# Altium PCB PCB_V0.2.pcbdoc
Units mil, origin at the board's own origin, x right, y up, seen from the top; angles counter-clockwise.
Board outline 2400 x 1790 mil, 2 copper layers (Top Layer, Bottom Layer); 38 components, 36 nets, 174 pads, 42 vias.
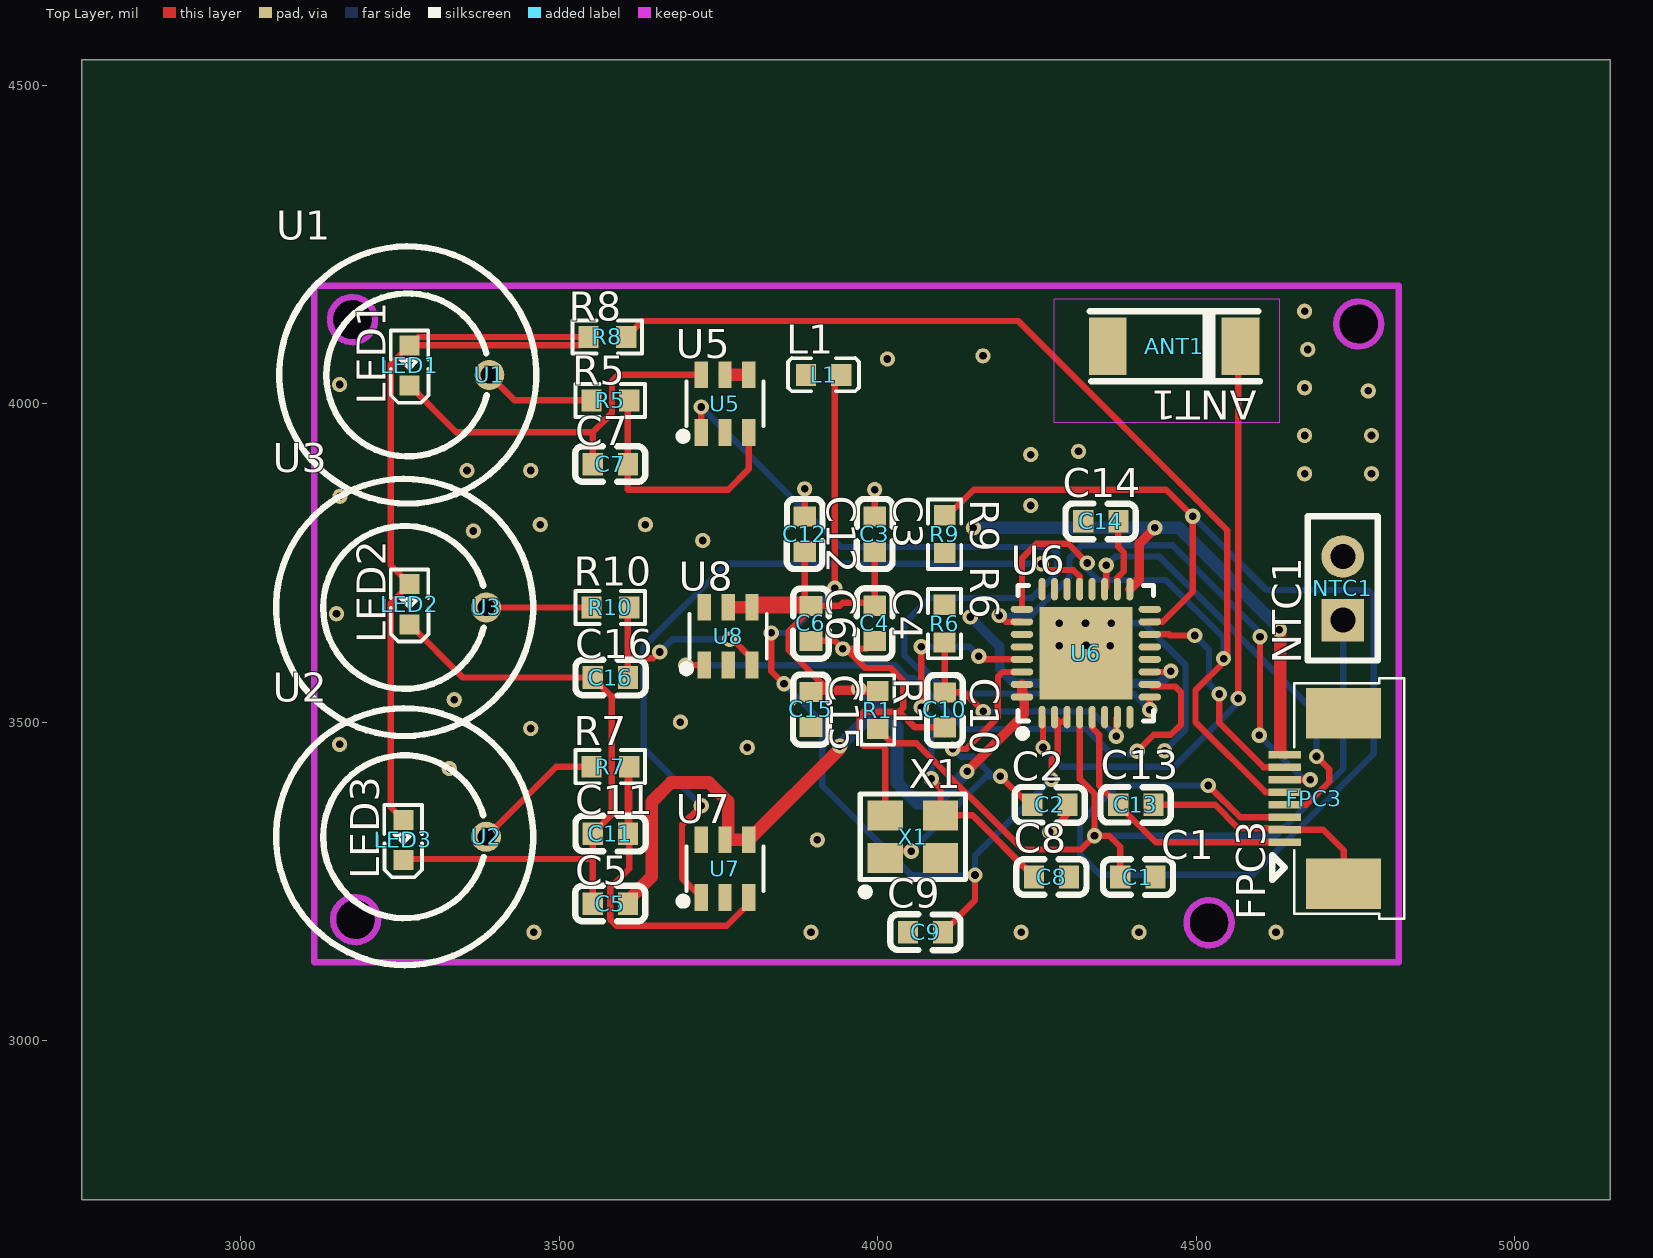
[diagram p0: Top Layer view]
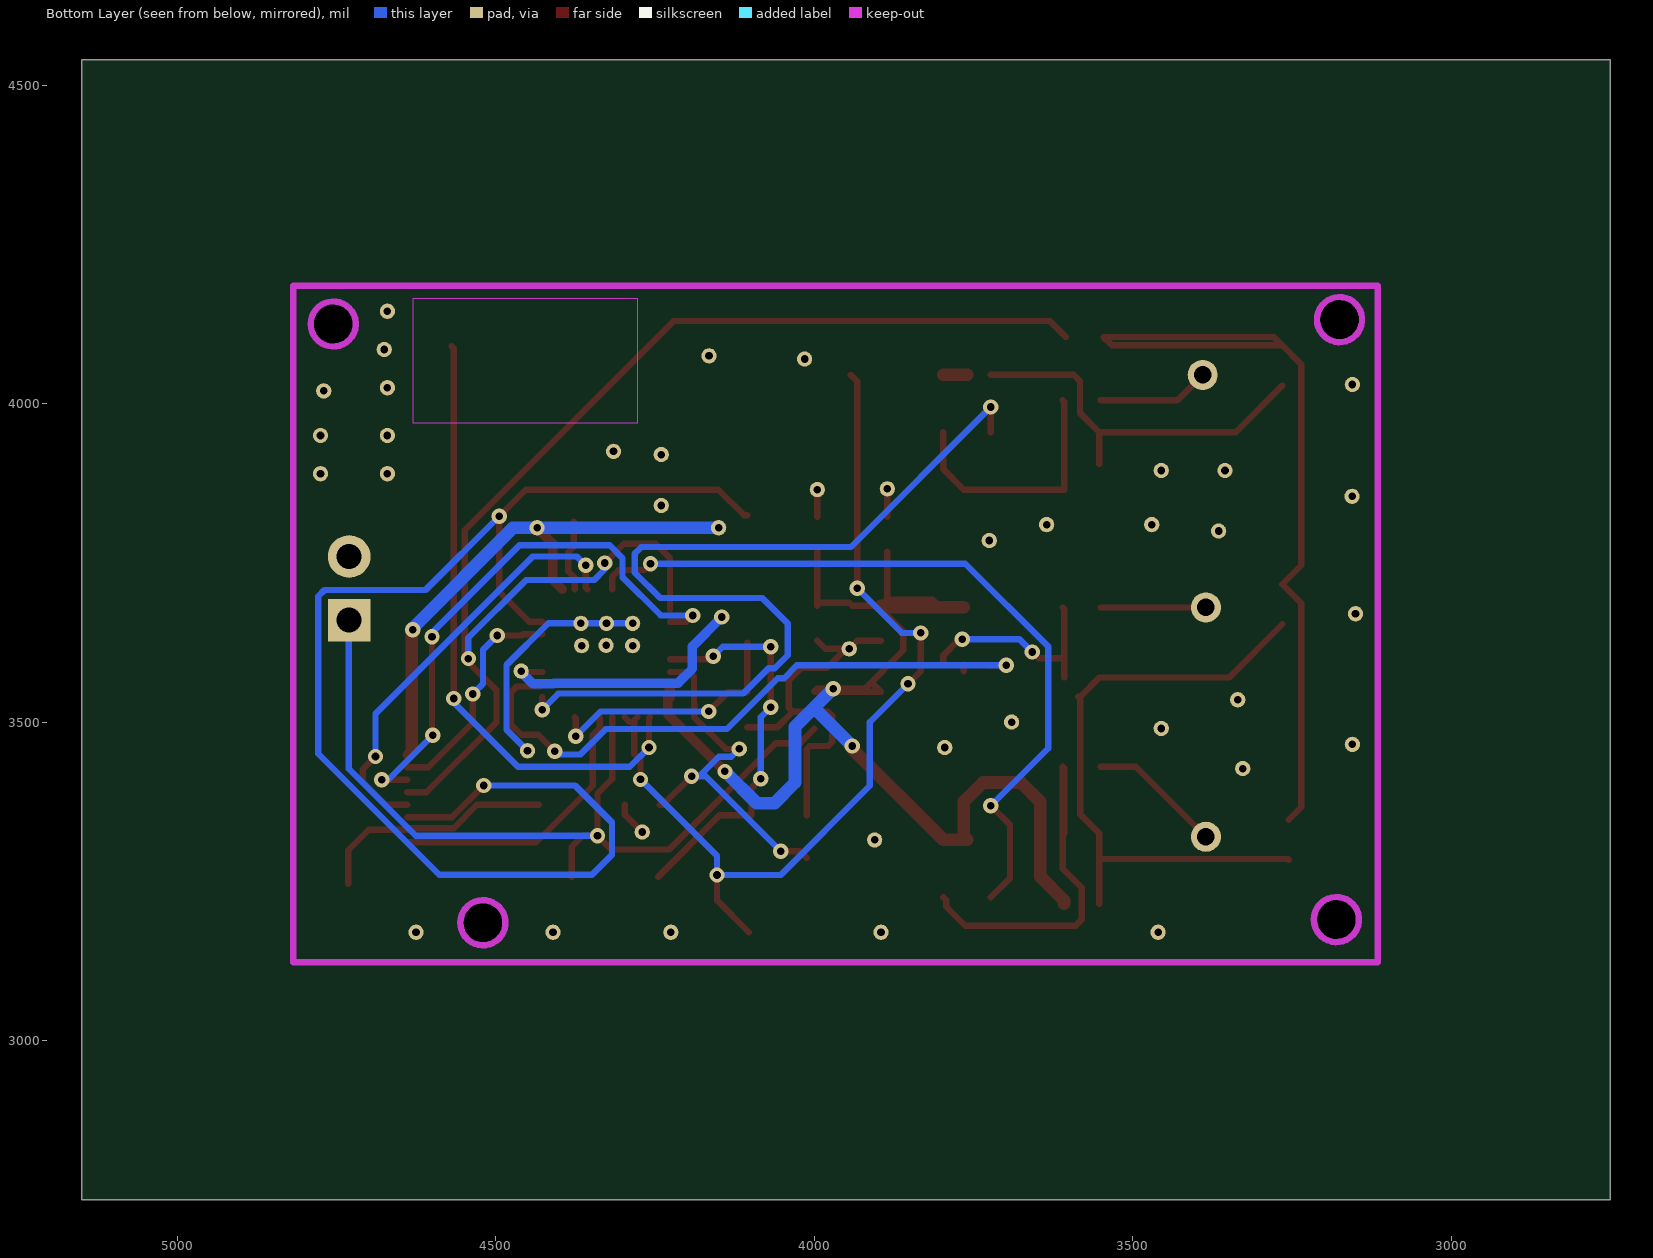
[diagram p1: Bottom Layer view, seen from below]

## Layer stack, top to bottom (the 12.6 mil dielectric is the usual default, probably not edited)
Top Layer: signal copper (thickness not stored)
Dielectric: dielectric 12.6, FR-4, Dk 4.8
Bottom Layer: signal copper (thickness not stored)

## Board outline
5150,2750 2750,2750 2750,4540 5150,4540
cut-out: 4555.43,3185 ccw(c4520,3184.67) 4484.57,3185 ccw(c4520,3185.33)
cut-out: 3215.43,3190 ccw(c3180,3189.67) 3144.57,3190 ccw(c3180,3190.33)
cut-out: 3210.54,4131.94 ccw(c3175.1,4131.94) 3139.67,4131.94 ccw(c3175.1,4131.94)
cut-out: 4790.43,4125 ccw(c4755,4124.67) 4719.57,4125 ccw(c4755,4125.33)

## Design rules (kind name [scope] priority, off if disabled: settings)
BoardOutlineClearance copperThickness1oz [All] p0: genericclearance=10 ignorepadtopadclearanceinfootprint=FALSE except(0: Arc-SplitContinuation Track-SplitContinuation SMDPad-SplitContinuation THPad-SplitContinuation Via-SplitContinuation Fill-SplitContinuation Poly-SplitContinuation Region-SplitContinuation Text-SplitContinuation; 6: Track-CutoutEdge SMDPad-CutoutEdge THPad-CutoutEdge Via-CutoutEdge Region-CutoutEdge; 11.8: Track-OutlineEdge SMDPad-OutlineEdge THPad-OutlineEdge Via-OutlineEdge Fill-OutlineEdge Region-OutlineEdge Poly-OutlineEdge Text-OutlineEdge Fill-CutoutEdge)
BoardOutlineClearance copperThickness2oz [All] p0: genericclearance=10 ignorepadtopadclearanceinfootprint=FALSE except(0: Arc-SplitContinuation Track-SplitContinuation SMDPad-SplitContinuation THPad-SplitContinuation Via-SplitContinuation Fill-SplitContinuation Poly-SplitContinuation Region-SplitContinuation Text-SplitContinuation; 6: Track-CutoutEdge SMDPad-CutoutEdge THPad-CutoutEdge Via-CutoutEdge Region-CutoutEdge; 11.8: Track-OutlineEdge SMDPad-OutlineEdge THPad-OutlineEdge Via-OutlineEdge Fill-OutlineEdge Region-OutlineEdge Poly-OutlineEdge Text-OutlineEdge Fill-CutoutEdge)
Clearance copperThickness1oz [(InNet('$1N1219') OR InNet('GPIO0') OR InNet('GND') OR InNet('$1N1185') OR InNet('3V3') OR InNet('$1N1977') OR InNet('$1N1184') OR InNet('$1N1223') OR InNet('CHIP_EN') OR InNet('$1N1981') OR InNet('ADC_VIN') OR InNet('VDD_SPI') OR InNet('$1N1980') OR InNet('GPIO8') OR InNet('DP1') OR InNet('DN1') OR InNet('GPIO12') OR InNet('GPIO9') OR InNet('$1N3691') OR InNet('$1N1982') OR InNet('$1N1984') OR InNet('$1N1983') OR InNet('GPIO4') OR InNet('GPIO2') OR InNet('GPIO3') OR InNet('GPIO5') OR InNet('GPIO6') OR InNet('GPIO7') OR InNet('GPIO10') OR InNet('GPIO13') OR InNet('GPIO14') OR InNet('GPIO15') OR InNet('GPIO16') OR InNet('GPIO17') OR InNet('U0R') OR InNet('U0T'))] p1: gap=7 ignorepadtopadclearanceinfootprint=FALSE except(4: Track-Track; 6: Track-SMDPad SMDPad-SMDPad Track-THPad SMDPad-THPad THPad-THPad Track-Via SMDPad-Via THPad-Via Via-Via SMDPad-Fill THPad-Fill Via-Fill Fill-Fill Track-Region SMDPad-Region THPad-Region Via-Region Region-Region Track-Poly SMDPad-Poly THPad-Poly Via-Poly Fill-Poly Region-Poly Poly-Poly Track-Text SMDPad-Text THPad-Text Via-Text Fill-Text Region-Text Poly-Text Text-Text; 6.9: Track-Hole SMDPad-Hole THPad-Hole Via-Hole Fill-Hole Region-Hole Poly-Hole Text-Hole Sheet-Hole; 11.8: Track-Fill Fill-Region Track-Sheet SMDPad-Sheet THPad-Sheet Via-Sheet Fill-Sheet Region-Sheet Poly-Sheet Text-Sheet)
Clearance copperThickness2oz [All] p1: gap=7 ignorepadtopadclearanceinfootprint=FALSE except(6: Track-SMDPad SMDPad-SMDPad Track-THPad SMDPad-THPad THPad-THPad Track-Via SMDPad-Via THPad-Via Via-Via SMDPad-Fill THPad-Fill Via-Fill Fill-Fill Track-Region SMDPad-Region THPad-Region Via-Region Region-Region Track-Poly SMDPad-Poly THPad-Poly Via-Poly Fill-Poly Region-Poly Poly-Poly Track-Text SMDPad-Text THPad-Text Via-Text Fill-Text Region-Text Poly-Text Text-Text; 6.9: Track-Hole SMDPad-Hole THPad-Hole Via-Hole Fill-Hole Region-Hole Poly-Hole Text-Hole Sheet-Hole; 8: Track-Track; 11.8: Track-Fill Fill-Region Track-Sheet SMDPad-Sheet THPad-Sheet Via-Sheet Fill-Sheet Region-Sheet Poly-Sheet Text-Sheet)
DiffPairsRouting differentialPair [All] p1: maxuncoupledlength=10 minlimit=6 maxlimit=6 mostfreqgap=6 toplayer_minwidth=5 toplayer_prefwidth=10 toplayer_maxwidth=100 bottomlayer_minwidth=5 bottomlayer_prefwidth=10 bottomlayer_maxwidth=100
PasteMaskExpansion pasteMaskExpansion [All] p1: expansion=0
PlaneConnect innerPlane [All] p1: planeconnectstyle=Relief reliefexpansion=20 reliefentries=4 reliefconductorwidth=10 reliefairgap=10
PolygonConnect copperRegion [All] p1: connectstyle=Relief reliefentries=4 reliefconductorwidth=10 polygonreliefangle="90 Angle" airgapwidth=10
RoutingVias viaSize [All] p1: viastyle="Through Hole" holewidth=12.0078 minholewidth=11.811 maxholewidth=248.0314 width=24.0158 minwidth=19.685 maxwidth=393.7008
SolderMaskExpansion solderMaskExpansion [All] p1: useseparateexpansions=TRUE expansion=2 expansionbottom=2
Width copperThickness1oz [All] p1: maxlimit=100 minlimit=5 preferedwidth=10
Width copperThickness2oz [All] p1: maxlimit=100 minlimit=8 preferedwidth=10

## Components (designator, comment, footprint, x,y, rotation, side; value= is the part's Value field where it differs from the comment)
ANT1 "CA-C03" ANT-SMD_CA-C03 4465,4090 r0 top
C1 "CGA0603X7R104K500JT" C0603 4408.11,3256.74 r180 top
C2 "CC0603KRNPO9BN100" C0603 4270,3370 r0 top
C3 "CC0603KRX7R9BB104" C0603 3995,3795 r270 top
C4 "CL10A106KP8NNNC" C0603 3995,3655.12 r90 top
C5 "CL10A105KA8NNNC" C0603 3580,3215 r0 top
C6 "CL10A106KP8NNNC" C0603 3895,3655 r90 top
C7 "CC0603JRNPO9BN150" C0603 3580,3905 r0 top
C8 "CC0603FRNPO9BN100" C0603 4272.77,3256.74 r0 top
C9 "CC0603KRX7R9BB104" C0603 4075,3170 r0 top
C10 "CL10A105KA8NNNC" C0603 4105.31,3519.18 r90 top
C11 "CC0603JRNPO9BN150" C0603 3580,3325 r180 top
C12 "CC0603KRX7R9BB104" C0603 3885,3795 r270 top
C13 "CGA0603X7R104K500JT" C0603 4405,3370 r0 top
C14 "CL10A106KP8NNNC" C0603 4350,3815 r0 top
C15 "CC0603KRX7R9BB104" C0603 3895,3520 r90 top
C16 "CC0603JRNPO9BN150" C0603 3580,3570 r180 top
FPC3 "F0501-T-08-20T-R" FPC-SMD_8P-P0.50_L4.4-W9.6 4685,3380 r90 top
L1 "SDCL1608C2N0STDF" l0603 3915,4045 r0 top
LED1 "LTST-C193TBKT-5A" LED0603-RD 3265,4060 r90 top
LED2 "LTST-C193TBKT-5A" LED0603-RD 3265,3685 r90 top
LED3 "LTST-C193TBKT-5A" LED0603-RD 3255,3315 r90 top
NTC1 "HDR-F_2.54_1x2P" HDR-TH_2P-P2.54-V-F 4730,3710 r90 top
R1 "0603WAF1002T5E" R0603 3999.66,3518.98 r90 top
R5 "0603WAF1001T5E" R0603 3580,4005 r0 top
R6 "0603WAF1002T5E" R0603 4104.66,3654.66 r270 top
R7 "0603WAF1001T5E" R0603 3580,3430 r0 top
R8 "0603WAF3300T5E" R0603 3575.34,4104.66 r180 top
R9 "0603WAF1002T5E" R0603 4105,3795 r90 top
R10 "0603WAF1001T5E" R0603 3580,3680 r0 top
U1 "F10-10-6.5-0.4P" TH_F10-10-6.5-0.4P 3390,4045 r0 top
U2 "F10-10-6.5-0.4P" TH_F10-10-6.5-0.4P 3385,3320 r0 top
U3 "F10-10-6.5-0.4P" TH_F10-10-6.5-0.4P 3385,3680 r0 top
U5 "JL423B" SOT-23-6_L2.9-W1.6-P0.95-LS2.8-BL-2 3760,4000 r0 top
U6 "ESP32-C3FN4" QFN-32_L5.0-W5.0-P0.50-BL-EP3.7 4326.69,3608.24 r0 top
U7 "JL423B" SOT-23-6_L2.9-W1.6-P0.95-LS2.8-BL-2 3760,3270 r0 top
U8 "JL423B" SOT-23-6_L2.9-W1.6-P0.95-LS2.8-BL-2 3765,3635 r0 top
X1 "X322540MPB4SI" OSC-SMD_4P-L3.2-W2.5-BL_SIT8008BI 4055,3320 r0 top

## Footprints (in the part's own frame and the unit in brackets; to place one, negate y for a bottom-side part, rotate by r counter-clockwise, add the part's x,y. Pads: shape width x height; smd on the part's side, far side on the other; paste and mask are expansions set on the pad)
ANT-SMD_CA-C03 [mm]
  rect 1.5x2.3 smd: 1(-2.65,0) 2(2.65,0)
  silkscreen extent -3.37,-1.4 3.43,1.4
C0603 [mm]
  rect 0.8x0.9 smd: 1(-0.7,0) 2(0.7,0)
  silkscreen extent -1.41,-0.71 1.39,0.72
FPC-SMD_8P-P0.50_L4.4-W9.6 [mm]
  rect 2x3 smd: 0(-3.4,-1.175) 0(3.4,-1.175)
  rect 0.3x1.3 smd: 1(-1.75,1.175) 2(-1.25,1.175) 3(-0.75,1.175) 4(-0.25,1.175) 5(0.25,1.175) 6(0.75,1.175) 7(1.25,1.175) 8(1.75,1.175)
  silkscreen extent -4.8,-3.6 4.8,1.68
HDR-TH_2P-P2.54-V-F [mm]
  rect 1.7x1.7 hole 1: 1(-1.27,0)
  round 1.7 hole 1: 2(1.27,0)
  silkscreen extent -2.88,-1.39 2.88,1.4
l0603 [mm]
  rect 0.8x0.864 smd: 1(-0.7,0) 2(0.7,0)
  silkscreen extent -1.42,-0.65 1.41,0.67
LED0603-RD [mm]
  rect 0.8x0.8 smd: 1(-0.799,0) 2(0.799,0)
  silkscreen extent -1.49,-0.75 1.39,0.76
OSC-SMD_4P-L3.2-W2.5-BL_SIT8008BI [mm]
  rect 1.4x1.2 smd: 1(-1.1,-0.85) 2(1.1,-0.85) 3(1.1,0.85) 4(-1.1,0.85)
  silkscreen extent -2.1,-2.35 2.1,1.7
QFN-32_L5.0-W5.0-P0.50-BL-EP3.7 [mm]
  oval 0.28x0.9 smd: 1(-1.75,-2.55) 2(-1.25,-2.55) 3(-0.749,-2.55) 4(-0.249,-2.55) 5(0.249,-2.55) 6(0.749,-2.55) 7(1.25,-2.55) 8(1.75,-2.55) 17(1.75,2.55) 18(1.25,2.55) 19(0.749,2.55) 20(0.249,2.55) 21(-0.249,2.55) 22(-0.749,2.55) 23(-1.25,2.55) 24(-1.75,2.55)
  oval 0.9x0.28 smd: 9(2.55,-1.75) 10(2.55,-1.25) 11(2.55,-0.749) 12(2.55,-0.249) 13(2.55,0.249) 14(2.55,0.749) 15(2.55,1.25) 16(2.55,1.75) 25(-2.55,1.75) 26(-2.55,1.25) 27(-2.55,0.749) 28(-2.55,0.249) 29(-2.55,-0.249) 30(-2.55,-0.749) 31(-2.55,-1.25) 32(-2.55,-1.75)
  rect 3.7x3.7 smd: 33(0,0)
  silkscreen extent -2.7,-3.35 2.7,2.7
R0603 [mil]
  rect 31.75x34.02 smd: 1(-29.66,0) 2(29.66,0)
  silkscreen extent -55,-26 55,26
SOT-23-6_L2.9-W1.6-P0.95-LS2.8-BL-2 [mil]
  rect 20.95x42.2 smd: 1(-37.4,-45.24) 2(0,-45.24) 3(37.4,-45.24) 4(37.4,45.24) 5(0,45.24) 6(-37.4,45.24)
  silkscreen extent -72,-57 61,35
TH_F10-10-6.5-0.4P [mm]
  round 1.2 hole 0.7: 1(0,0)
  silkscreen extent -8.37,-5.13 1.87,5.13

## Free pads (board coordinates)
  round 24 hole 12: 1(3150,3670) 1(3155,3465) 1(3155,4030) 1(3155.44,3854.44) 1(3327.18,3427.02) 1(3335,3535) 1(3355,3895) 1(3365,3800) 1(3455,3490) 1(3455,3895) 1(3460,3170) 1(3470,3810) 1(3635,3810) 1(3690,3500) 1(3725,3785) 1(3795,3460) 1(3885.11,3866.2) 1(3895,3170) 1(3905,3315) 1(3945,3615) 1(3995,3865) 1(4015,4070) 1(4150,3805) 1(4165,4075) 1(4225,3170) 1(4240,3920) 1(4270,3327.37) 1(4285,3620) 1(4285,3655) 1(4315,3925) 1(4326.04,3655) 1(4326.69,3620.51) 1(4365,3620) 1(4366.17,3655) 1(4410,3170) 1(4435,3805) 1(4450,3455) 1(4460,3580) 1(4625,3170) 1(4670,3890) 1(4670,3950) 1(4670,4025) 1(4670,4145) 1(4675,4085) 1(4770,4020) 1(4775,3890) 1(4775,3950) 2(4240,3840)

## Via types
v1: diameter 24.02, hole 12.01, Top Layer to Bottom Layer, 42 vias

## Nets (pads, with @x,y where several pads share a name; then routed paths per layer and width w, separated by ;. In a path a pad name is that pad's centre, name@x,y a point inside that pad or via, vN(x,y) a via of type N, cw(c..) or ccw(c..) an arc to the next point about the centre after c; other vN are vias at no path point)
3V3: C3.2 C4.2 C5.2 C6.2 C12.2 C15.2 FPC3.8 L1.1 pad.1@4150,3805 pad.1@4435,3805 pad.1@4460,3580 R1.2 R6.1 R9.1 U5.4 U5.5 U6.11 U6.17 U6.31 U6.32 U7.4 U7.5 U8.4 U8.5 | length 3419.2
  Top Layer w9.92: U6.32 4230.12,3542.56 4230.12,3555.21 U6.31 ; U6.11 pad.1@4460.24,3578.74
  Top Layer w10: U8.4 3814.72,3692.56 C6.2@3885,3692.56 ; C12.2 C6.2@3885,3692.56 ; C15.2@3910,3562.56 C15.2 3998.58,3547.56 R1.2 3995.74,3552.56 v1(3970.12,3552.56) 3920.12,3552.56 3860.12,3612.56 3860.12,3642.56 C6.2@3900.12,3682.56 ; C4.2 C4.2@3995,3687.44 ; C3.2 C4.2@3995,3687.44 ; C6.2@3885,3692.56 C6.2 C6.2@3900.12,3682.56 ; C6.2@3900.12,3682.56 3940.12,3682.56 3945,3687.44 C4.2@3995,3687.44
  Top Layer w15: v1(4140.12,3422.56) 4230.12,3512.56 U6.32@4230.12,3542.56 ; U6.32 U6.31 ; U6.17 4410.59,3723.64 4410.59,3780.59 pad.1@4435,3805 ; 4631.73,3455.9 FPC3.8
  Top Layer w20: C5.2 3607.56,3220 3645,3257.44 3645,3375 3675.24,3405.24 3735,3405.24 3765,3375.24 3765,3320.24 U7.5 U7.4 3940.12,3457.96 v1(3940.12,3462.56) ; U5.5 U5.4 ; U8.5 U8.4 3892.68,3680.24 C6.2 ; v1(4630,3645) 4631.73,3643.27 4631.73,3455.9
  Bottom Layer w15: v1(4145,3665) 4191.3,3618.7 4191.3,3583.7 4213.76,3561.24 4408.49,3561.24 4409.73,3560 4441.5,3560 pad.1@4460.24,3578.74
  Bottom Layer w20: v1(3940.12,3462.56) 4000.12,3522.56 ; v1(3970.12,3552.56) 4000.12,3522.56 ; v1(4140.12,3422.56) 4090.12,3372.56 4062.44,3372.56 4030,3405 4030,3492.68 4000.12,3522.56 ; pad.1@4150,3805 4435,3805 4472.95,3805 4630,3647.95 v1(4630,3645)
$1N1184: C8.1 U6.29 X1.3 | length 630.7
  Top Layer w9.92: v1(4068.31,3523.47) v1(4068.31,3618.47) ; v1(4083.9,3410.93) 4098.31,3396.53 X1.3 ; v1(4158.31,3603.47) 4163.34,3598.44 U6.29
  Top Layer w10: X1.3 4148.49,3353.47 C8.1
  Bottom Layer w9.92: v1(4068.31,3523.47) 4083.9,3507.87 v1(4083.9,3410.93) ; v1(4068.31,3618.47) 4143.31,3618.47 v1(4158.31,3603.47)
$1N1185: C2.1 U6.30 X1.1 | length 578.7
  Top Layer w9.92: v1(4117.65,3457.88) 4138.91,3457.88 4188.26,3507.24 4188.26,3528.49 4188.69,3528.92 4188.69,3571.14 4196.29,3578.74 U6.30 ; v1(4192.44,3415) 4237.44,3370 C2.1
  Top Layer w10: X1.1 4022.44,3297.28 v1(4052.44,3297.28)
  Bottom Layer w9.92: v1(4117.65,3457.88) 4130.02,3445.51 4149.63,3445.51 4180.14,3415
  Bottom Layer w10: v1(4052.44,3297.28) 4170.15,3415 4180.14,3415 v1(4192.44,3415)
$1N1219: ANT1.2 U6.1 | length 969.8
  Top Layer w9.92: U6.1 4259.33,3506.3 v1(4259.33,3460) ; v1(4565.79,3537.01) 4565.79,4086.46 ANT1.2
  Bottom Layer w9.92: v1(4259.33,3460) 4289.33,3430 4465,3430 4565.79,3530.79 v1(4565.79,3537.01)
$1N1223: C9.2 L1.2 U6.2 U6.3 | length 1471.6
  Top Layer w9.92: v1(3832.56,3640) 3832.56,3580 v1(3852.56,3560) ; v1(3932.56,3710) 3932.56,4035.01 L1.2 ; C9.2 4152.56,3220 v1(4152.56,3260) ; v1(4272.56,3410) 4272.56,3440 4282.56,3450 U6.2@4282.56,3500 ; U6.2 4282.56,3502.77 U6.2@4282.56,3500 ; U6.3 4289.35,3500 U6.2@4282.56,3500
  Bottom Layer w9.92: v1(3832.56,3640) 3862.56,3640 v1(3932.56,3710) ; v1(3852.56,3560) 3912.56,3500 3912.56,3400 4052.56,3260 v1(4152.56,3260) 4152.56,3290 v1(4272.56,3410)
$1N1977: C7.2 R5.2 U5.3 | length 401.5
  Top Layer w10: R5.2 3607.56,4002.9 C7.2 3607.56,3865 3765,3865 3797.4,3897.4 U5.3
$1N1980: C16.1 R10.2 U8.3 | length 340.7
  Top Layer w10: C16.1 3607.56,3600 ; R10.2 3607.56,3677.9 3607.56,3600 ; v1(3657.56,3610) 3647.56,3600 3607.56,3600 ; v1(3767.56,3630) 3772.16,3630 3797.56,3604.6 3797.56,3594.6 U8.3
  Bottom Layer w10: v1(3657.56,3610) 3677.56,3630 v1(3767.56,3630)
$1N1981: C11.1 R7.2 U7.3 | length 604.6
  Top Layer w10: C11.1 3607.56,3427.9 R7.2 3609.66,3270 3579.66,3240 3579.66,3190 3589.66,3180 3762.64,3180 3792.64,3210 3792.64,3220 U7.3
$1N1982: R5.1 U1.1 | length 176.9
  Top Layer w10: U1.1 3430,4005 R5.1
$1N1983: R10.1 U3.1 | length 165.3
  Top Layer w10: U3.1 R10.1
$1N1984: R7.1 U2.1 | length 210.9
  Top Layer w10: U2.1 3495,3430 R7.1
$1N3691: LED1.2 LED2.2 LED3.2 R8.2 | length 1362.9
  Top Layer w10: LED3.2 3234.99,3366.47 3234.99,3686.47 LED2.2 3234.99,3746.47 3234.99,4061.47 LED1.2 ; LED1.2 3278.18,4104.66 R8.2 3532.49,4091.47 LED1.2
ADC_VIN: C13.1 FPC3.1 U6.5 | length 440.5
  Top Layer w10: U6.5 4336.49,3490.95 4347.44,3480 4347.44,3400 C13.1 4436.34,3311.11 FPC3.1
CHIP_EN: C10.2 R6.2 U6.7 | length 406.7
  Top Layer w9.92: C10.2 4135.31,3546.74 v1(4165.31,3516.74) ; v1(4374.21,3477.84) 4374.21,3506.16 U6.7
  Top Layer w10: R6.2 4105.31,3624.36 C10.2
  Bottom Layer w9.92: v1(4165.31,3516.74) 4335.31,3516.74 v1(4374.21,3477.84)
DN1: FPC3.5 R8.1 U6.25 | length 2103.4
  Top Layer w9.92: R8.1 3630,4129.66 4220.34,4129.66 4548.66,3801.34 4548.66,3605.51 v1(4542.83,3599.68) 4542.83,3593.94 4498.74,3549.84 4498.74,3499.84 4608.74,3389.84 FPC3.5 ; U6.25 4226.29,3757.4 4248.74,3779.84 4298.74,3779.84 v1(4328.74,3749.84)
  Bottom Layer w9.92: v1(4328.74,3749.84) 4328.74,3739.84 4345.45,3723.14 4451.86,3723.14 4542.83,3632.17 v1(4542.83,3599.68)
DP1: FPC3.6 U6.26 | length 878.8
  Top Layer w9.92: v1(4190.83,3667.44) 4200.83,3657.44 U6.26 ; v1(4598.74,3479.53) 4600,3480.78 v1(4600,3634.18) ; FPC3.6 v1(4678.74,3409.53)
  Bottom Layer w9.92: v1(4190.83,3667.44) 4240.83,3667.44 4300.83,3727.44 4300.83,3757.44 4320.83,3777.44 4462.56,3777.44 4600,3640 v1(4600,3634.18) ; v1(4598.74,3479.53) 4668.74,3409.53 v1(4678.74,3409.53)
GND: C1.1 C2.2 C3.1 C4.1 C5.1 C6.1 C7.1 C8.2 C9.1 C10.1 C11.2 C12.1 C13.2 C14.1 C15.1 C16.2 FPC3.0 FPC3.2 LED1.1 LED2.1 LED3.1 NTC1.2 pad.1@3150,3670 pad.1@3155,3465 pad.1@3155,4030 pad.1@3155.44,3854.44 pad.1@3327.18,3427.02 pad.1@3335,3535 pad.1@3355,3895 pad.1@3365,3800 pad.1@3455,3490 pad.1@3455,3895 pad.1@3460,3170 pad.1@3470,3810 pad.1@3635,3810 pad.1@3690,3500 pad.1@3725,3785 pad.1@3795,3460 pad.1@3885.11,3866.2 pad.1@3895,3170 pad.1@3905,3315 pad.1@3945,3615 pad.1@3995,3865 pad.1@4015,4070 pad.1@4165,4075 pad.1@4225,3170 pad.1@4240,3920 pad.1@4270,3327.37 pad.1@4285,3620 pad.1@4285,3655 pad.1@4315,3925 pad.1@4326.04,3655 pad.1@4326.69,3620.51 pad.1@4365,3620 pad.1@4366.17,3655 pad.1@4410,3170 pad.1@4450,3455 pad.1@4625,3170 pad.1@4670,3890 pad.1@4670,3950 pad.1@4670,4025 pad.1@4670,4145 pad.1@4675,4085 pad.1@4770,4020 pad.1@4775,3890 pad.1@4775,3950 pad.2 U5.2 U5.6 U6.33 U7.2 U7.6 U8.2 U8.6 X1.2 X1.4 | length 3121.7
  Top Layer w10: LED3.1 3256.48,3285 3552.44,3285 ; LED2.1 3348.53,3570 C16.2 3582.44,3540 3585.24,3540 3582.44,3537.2 3582.44,3355 C11.2 3552.44,3285 ; LED1.1 3338.29,3955.24 3552.6,3955.24 ; C5.1 3552.44,3285 ; C7.1@3552.6,3905.16 3552.6,3955.24 ; U5.6 3592.6,4045.24 3582.6,4035.24 3582.6,3985.24 3552.6,3955.24 ; U8.2 3765,3579.76 U8.2@3765.29,3579.76 ; C12.1 3885,3866.09 pad.1@3885.11,3866.2 ; C6.1 3932.56,3627.44 3945,3615 pad.1@3950,3615 ; C4.1 3982.44,3615 pad.1@3950,3615 ; C3.1 pad.1@3995,3865 ; X1.4 4011.69,3457.52 4006.75,3462.46 3978.1,3462.46 3971.67,3468.89 3971.67,3509.75 3978.1,3516.18 4033.46,3516.18 4033.64,3516.36 ; C10.1 4058.38,3491.62 4033.64,3516.36 ; pad.1@4270,3327.37 4297.56,3354.93 C2.2 ; C13.2 4529.45,3370 4565.86,3333.59 4635.94,3333.59 FPC3.2 4699.22,3330.78 4731.26,3298.74 FPC3.0@4731.26,3246.14 ; pad.1@3950,3615 3980,3585 4020,3585 4040,3565 4040,3522.72 4033.64,3516.36
  Bottom Layer w10: pad.1@4285,3655 4326.04,3655 4366.17,3655 4417.5,3655 4482.98,3589.52 4482.98,3487.98 pad.1@4450,3455
GPIO0: C1.2 NTC1.1 R1.1 U6.4 | length 1386.4
  Top Layer w9.92: R1.1 4022.24,3466.74 4060.55,3466.74 4227.3,3300 4318.81,3300 v1(4340.24,3321.43) 4340.24,3387.43 4316.89,3410.78 4316.89,3483.11
  Top Layer w10: 4316.89,3483.11 U6.4 ; v1(4340.24,3321.43) 4363.57,3321.43 4380.55,3304.45 C1.2
  Bottom Layer w9.92: v1(4340.24,3321.43) 4625.24,3321.43 4730.55,3426.74 4730.55,3659.45 NTC1.1
GPIO2: U6.6
GPIO3: U6.8
GPIO4: U5.1 U6.9 | length 1488.3
  Top Layer w9.92: U5.1 v1(3722.6,3994.76) ; v1(4427.09,3519.34) U6.9
  Bottom Layer w9.92: v1(3722.6,3994.76) 3942.6,3774.76 4271.67,3774.76 4281.67,3764.76 4281.67,3734.76 4241.67,3694.76 4081.67,3694.76 4041.67,3654.76 4041.67,3604.76 4061.67,3584.76 4071.67,3584.76 4111.67,3544.76 4401.67,3544.76 v1(4427.09,3519.34)
GPIO5: U6.10 U8.1 | length 989.5
  Top Layer w9.92: v1(3698.32,3589.04) 3726.88,3589.04 U8.1 ; v1(4407.09,3454.04) 4433.05,3480 4460,3480 4475.96,3495.96 4475.96,3546.95 4467.12,3555.8 4430.33,3555.8 U6.10
  Bottom Layer w9.92: v1(3698.32,3589.04) 4027.09,3589.04 4047.09,3569.04 4057.09,3569.04 4137.09,3489.04 4327.09,3489.04 4367.09,3449.04 4402.09,3449.04 v1(4407.09,3454.04)
GPIO6: U6.12
GPIO7: U6.13
GPIO8: FPC3.7 U6.14 | length 355.9
  Top Layer w9.92: U6.14 4457.09,3637.74 4458.95,3635.87 v1(4497.76,3635.87) ; v1(4535.79,3544.22) 4535.79,3499.04 4605.61,3429.22 FPC3.7
  Bottom Layer w9.92: v1(4497.76,3635.87) 4519.88,3613.75 4519.88,3560.12 v1(4535.79,3544.22)
GPIO9: FPC3.3 R9.2 U6.15 | length 2181.9
  Top Layer w9.92: R9.2 4110,3824.66 4150.34,3865 4452.54,3865 v1(4494.45,3823.09) 4494.45,3704.8 4447.09,3657.44 U6.15 ; v1(4518.74,3400.47) 4568.74,3350.47 FPC3.3
  Bottom Layer w9.92: v1(4494.45,3823.09) 4610.1,3707.44 4768.74,3707.44 4778.74,3697.44 4778.74,3450.47 4588.74,3260.47 4348.74,3260.47 4317.29,3291.92 4317.29,3342.29 4375.48,3400.47 v1(4518.74,3400.47)
GPIO10: U6.16
GPIO12: FPC3.4 U6.19 | length 676.6
  Top Layer w9.92: U6.19 4358.74,3711.19 v1(4358.74,3746.09) ; FPC3.4 4672.81,3370.16 4708.74,3406.09 4708.74,3426.09 v1(4688.74,3446.09)
  Bottom Layer w9.92: v1(4358.74,3746.09) 4372.65,3760 4441.72,3760 4688.74,3512.98 v1(4688.74,3446.09)
GPIO13: U6.20
GPIO14: U6.21 U7.1 | length 1222.4
  Top Layer w9.92: U7.1 3692.6,3254.76 3692.6,3338.64 v1(3722.6,3368.64) ; v1(4256.89,3748.64) 4266.89,3738.64 4306.89,3738.64 4316.89,3728.64 U6.21
  Bottom Layer w9.92: v1(3722.6,3368.64) 3632.6,3458.64 3632.6,3618.64 3762.6,3748.64 v1(4256.89,3748.64)
GPIO15: U6.22
GPIO16: U6.23
GPIO17: U6.24
U0R: U6.27
U0T: U6.28
VDD_SPI: C14.2 U6.18 | length 114
  Top Layer w9.92: U6.18 4375.89,3726.67 4385.89,3736.67 4385.89,3766.67 4377.56,3775 C14.2
pads on no net: ANT1.1

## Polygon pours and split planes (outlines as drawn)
GND on Bottom Layer (solid, remove dead copper, pour order 10): 3005,4260 4885,4260 4885,3015 3005,3015
GND on Top Layer (solid, remove dead copper, pour order 6): 3000,4290 4900,4290 4900,3000 3000,3000
3V3 on Top Layer (solid, remove dead copper, pour order 0): 3745,4085 3905,4085 3905,3994.59 3745.41,3994.59 3745,3995
3V3 on Top Layer (solid, remove dead copper, pour order 2): 3825.21,3994.59 3825.21,3529.79 3830,3525 4035,3525 4040,3520 4040,3635 4055,3650 4181.6,3650 4181.6,3996.6 4185,4000 3830,4000 3825,3995 3825,3994.59
3V3 on Top Layer (solid, remove dead copper, pour order 4): 3758.05,3710.38 3758.43,3710 3845,3710 3845,3635.24 3836.28,3626.52 3817.79,3645 3750,3645 3750,3710.38

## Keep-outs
Board Outline Layer:
  circle w1: c4520,3185 r35.43
  circle w10: c4520,3185 r35.43
  circle w1: c3180,3190 r35.43
  circle w10: c3180,3190 r35.43
  circle w1: c3175.11,4131.94 r35.43
  circle w10: c3175.11,4131.94 r35.43
  circle w1: c4755,4125 r35.43
  circle w10: c4755,4125 r35.43
  region: 4276.91,4165 4630,4165 4630,3970 4276.91,3970
  lines w10: 3115,3123 4818,3123 4818,4185 3115,4185 3115,3123

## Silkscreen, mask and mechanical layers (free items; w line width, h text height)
Mechanical Layer:
  circle w1: c4520,3185 r35.43
  circle w1: c3180,3190 r35.43
  circle w1: c3175.11,4131.94 r35.43
  circle w1: c4755,4125 r35.43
